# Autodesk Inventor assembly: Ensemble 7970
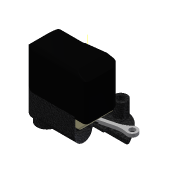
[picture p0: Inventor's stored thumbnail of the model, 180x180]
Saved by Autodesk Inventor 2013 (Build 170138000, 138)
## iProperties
Created: 2011-10
Part Number: Ensemble 7970
Document SubType Name: Assembly
Designer: Laur
Author: Laur
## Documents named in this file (12)
- D:\_an13-14\FORMULAIRE_2014\Sujet E4 Poissy 2014\Modélisation_7970_shimano_2014\Ensemble 7970.iam
- D:\_an13-14\FORMULAIRE_2014\Sujet E4 Poissy 2014\Modélisation_7970_shimano_2014\Fond_boitier.ipt
- D:\_an13-14\FORMULAIRE_2014\Sujet E4 Poissy 2014\Modélisation_7970_shimano_2014\Sous-ensemble 7970.iam
- D:\_an13-14\FORMULAIRE_2014\Sujet E4 Poissy 2014\Modélisation_7970_shimano_2014\éléments standards\ISO 3601-1(5)\ISO 3601-1 - A 0035 G 4(5).ipt
- D:\_an13-14\FORMULAIRE_2014\Sujet E4 Poissy 2014\Modélisation_7970_shimano_2014\mobile de sortie.iam
- D:\_an13-14\FORMULAIRE_2014\Sujet E4 Poissy 2014\Modélisation_7970_shimano_2014\Montage PCB_FD.iam
- D:\_an13-14\FORMULAIRE_2014\Sujet E4 Poissy 2014\Modélisation_7970_shimano_2014\Support pistes capteur angulaire.ipt
- D:\_an13-14\FORMULAIRE_2014\Sujet E4 Poissy 2014\Modélisation_7970_shimano_2014\support_curseur_equipe.iam
- D:\_an13-14\FORMULAIRE_2014\Sujet E4 Poissy 2014\Modélisation_7970_shimano_2014\biellette.ipt
- D:\_an13-14\FORMULAIRE_2014\Sujet E4 Poissy 2014\Modélisation_7970_shimano_2014\PalierØ4-2_normal.ipt
- D:\_an13-14\FORMULAIRE_2014\Sujet E4 Poissy 2014\Modélisation_7970_shimano_2014\PalierØ4-2_etroit.ipt
- D:\_an13-14\FORMULAIRE_2014\Sujet E4 Poissy 2014\Modélisation_7970_shimano_2014\couvercle\couvercle\Couvercle.ipt
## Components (12 placed, 11 different names)
1. Fond_boitier:1 — appui plan platine/boîtier, coaxialité axe de sortie, orientation platine boîtier, coaxialité palier / fond boîtier, appui plan palier / fond boîtier, Placage:17, Tangente:2
2. Sous-ensemble 7970:1 [sub-assembly] — appui plan platine/boîtier, coaxialité axe de sortie, orientation platine boîtier, coaxialité joint/logement, pos axiale joint/logement, Logement palier / platine, appui plan PCB / cage, centrage PBC / pilier1 cage, appui plan, centrage pilier1 Map, centrage pilier2 Map, centrage PCB / pilier2 cage, Placage:18, Placage:20
3. ISO 3601-1 hydraulique (Intérieurs) A 0035 G:1 — coaxialité joint/logement, pos axiale joint/logement
4. PalierØ4-2_normal:1 — Logement palier / platine, Logement:2
5. mobile de sortie:1 [sub-assembly] — Logement:2, centrage support curseur/arbre de sortie, pos angulaire plot / secteur denté, appui plan support / secteur denté, pivot biellette / maneton, Placage:19
6. Montage PCB_FD:1 [sub-assembly] — appui plan PCB / cage, centrage PBC / pilier1 cage, centrage PCB / pilier2 cage
7. Support pistes capteur angulaire:1 — appui plan, centrage pilier1 Map, centrage pilier2 Map
8. support_curseur_equipe:1 [sub-assembly] — centrage support curseur/arbre de sortie, pos angulaire plot / secteur denté, appui plan support / secteur denté
9. biellette:1 — pivot biellette / maneton
10. PalierØ4-2_etroit:1 — coaxialité palier / fond boîtier, appui plan palier / fond boîtier
11. ISO 3601-1 hydraulique (Intérieurs) A 0035 G:2 — Placage:17, Tangente:2
12. Couvercle:1 — Placage:18, Placage:19, Placage:20
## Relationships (24: Mate 18, Insert 3, Tangent 2, Angle 1)
- appui plan platine/boîtier [Mate]: Fond_boitier:1 ↔ Sous-ensemble 7970:1
- coaxialité axe de sortie [Mate]: Fond_boitier:1 ↔ Sous-ensemble 7970:1
- orientation platine boîtier [Angle]: Fond_boitier:1 ↔ Sous-ensemble 7970:1
- coaxialité joint/logement [Mate]: Sous-ensemble 7970:1 ↔ ISO 3601-1 hydraulique (Intérieurs) A 0035 G:1
- pos axiale joint/logement [Tangent]: Sous-ensemble 7970:1 ↔ ISO 3601-1 hydraulique (Intérieurs) A 0035 G:1
- Logement palier / platine [Insert]: Sous-ensemble 7970:1 ↔ PalierØ4-2_normal:1
- Logement:2 [Insert]: PalierØ4-2_normal:1 ↔ mobile de sortie:1
- appui plan PCB / cage [Mate]: Sous-ensemble 7970:1 ↔ Montage PCB_FD:1
- centrage PBC / pilier1 cage [Mate]: Sous-ensemble 7970:1 ↔ Montage PCB_FD:1
- appui plan [Mate]: Sous-ensemble 7970:1 ↔ Support pistes capteur angulaire:1
- centrage pilier1 Map [Mate]: Sous-ensemble 7970:1 ↔ Support pistes capteur angulaire:1
- centrage pilier2 Map [Mate]: Sous-ensemble 7970:1 ↔ Support pistes capteur angulaire:1
- centrage support curseur/arbre de sortie [Mate]: mobile de sortie:1 ↔ support_curseur_equipe:1
- pos angulaire plot / secteur denté [Mate]: mobile de sortie:1 ↔ support_curseur_equipe:1
- appui plan support / secteur denté [Mate]: mobile de sortie:1 ↔ support_curseur_equipe:1
- centrage PCB / pilier2 cage [Mate]: Sous-ensemble 7970:1 ↔ Montage PCB_FD:1
- pivot biellette / maneton [Insert]: mobile de sortie:1 ↔ biellette:1
- coaxialité palier / fond boîtier [Mate]: Fond_boitier:1 ↔ PalierØ4-2_etroit:1
- appui plan palier / fond boîtier [Mate]: Fond_boitier:1 ↔ PalierØ4-2_etroit:1
- Placage:17 [Mate]: Fond_boitier:1 ↔ ISO 3601-1 hydraulique (Intérieurs) A 0035 G:2
- Tangente:2: Fond_boitier:1 ↔ ISO 3601-1 hydraulique (Intérieurs) A 0035 G:2
- Placage:18 [Mate]: Sous-ensemble 7970:1 ↔ Couvercle:1
- Placage:19 [Mate]: mobile de sortie:1 ↔ Couvercle:1
- Placage:20 [Mate]: Sous-ensemble 7970:1 ↔ Couvercle:1
